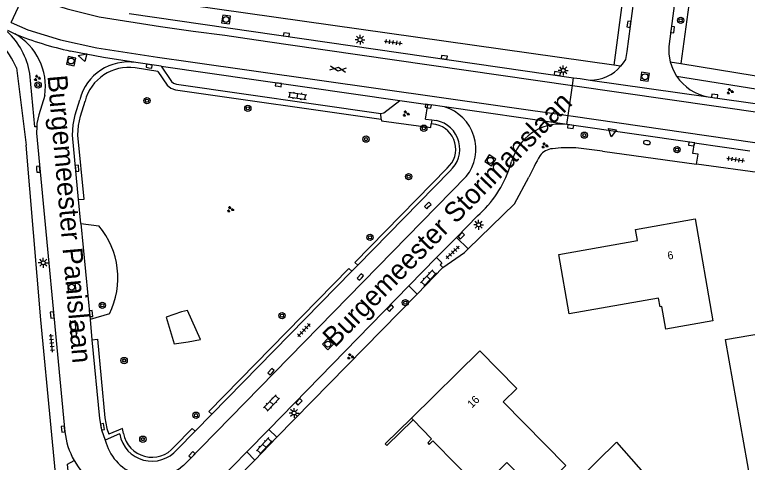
# Model space of a CAD drawing. Extents: x 136000 to 138005, y 398500 to 400500.
# Drawn here: x 137759.2 to 137852, y 398873.8 to 398930.5 of the extents above; entities that cross this region are included whole.
import ezdxf

# ---------------------------------------------------------------- set-up
doc = ezdxf.new("R2010")
doc.units = 0
for name, color, linetype in [('gg-afsc-erfafscheiding', 7, 'Continuous'), ('gg-afsc-muur', 7, 'Continuous'), ('gg-anno-huisnummerreeks BGT', 7, 'Continuous'), ('gg-anno-openbare ruimte label', 7, 'Continuous'), ('gg-bbg-gedigitaliseerde bebouwing', 7, 'Continuous'), ('gg-bbg-gedigitaliseerde bijgebouw', 7, 'Continuous'), ('gg-bbg-hoofdgebouw', 7, 'Continuous'), ('gg-knt-verharding', 7, 'Continuous'), ('gg-knt-verharding nz', 7, 'Continuous'), ('gt-grn-groengrens', 7, 'Continuous'), ('gt-grn-vlakafsluiter', 7, 'Continuous'), ('gt-grn-weggrens', 7, 'Continuous'), ('gt-symb-boom', 7, 'Continuous'), ('gt-symb-brandkraan', 7, 'Continuous'), ('gt-symb-gesloten verharding', 7, 'Continuous'), ('gt-symb-groenvak', 7, 'Continuous'), ('gt-symb-klinker verharding', 7, 'Continuous'), ('gt-symb-kolk', 7, 'Continuous'), ('gt-symb-lichtmast', 7, 'Continuous'), ('gt-symb-rioolschacht', 7, 'Continuous'), ('gt-symb-tegel verharding', 7, 'Continuous'), ('gt-symb-waterafsluiter', 7, 'Continuous')]:
    doc.layers.add(name, color=color, linetype=linetype)

# ---------------------------------------------------------------- blocks, each defined once
blk = doc.blocks.new('gt0-BOOM')
at = {"layer": 'gt-symb-boom'}
for radius in [0.4, 0.2]:
    blk.add_circle((0, 0), radius, dxfattribs=at)
blk = doc.blocks.new('gt0-KOLK')
at = {"layer": 'gt-symb-kolk'}
blk.add_lwpolyline([(0, 0), (0.375, 0), (0.375, 0.4), (-0.375, 0.4), (-0.375, 0), (0, 0)], dxfattribs=at)
blk = doc.blocks.new('gt0-LMAST')
at = {"layer": 'gt-symb-lichtmast'}
for p, q in [((-0.182, 0.173), (-0.447, 0.438)), ((-0.005, 0.246), (-0.005, 0.621)), ((0.172, 0.173), (0.437, 0.438)), ((-0.255, -0.004), (-0.63, -0.004)), ((-0.182, -0.181), (-0.447, -0.446)), ((-0.005, -0.254), (-0.005, -0.629)), ((0.437, -0.446), (0.172, -0.181)), ((0.245, -0.004), (0.62, -0.004))]:
    blk.add_line(p, q, dxfattribs=at)
blk.add_circle((-0.005, -0.004), 0.25, dxfattribs=at)
blk = doc.blocks.new('gt0-RS')
at = {"layer": 'gt-symb-rioolschacht'}
blk.add_lwpolyline([(-0.5, -0.5), (0.5, -0.5), (0.5, 0.5), (-0.5, 0.5)], close=True, dxfattribs=at)
blk.add_circle((0, 0), 0.375, dxfattribs=at)
blk = doc.blocks.new('gt0-WAFSL')
at = {"layer": 'gt-symb-waterafsluiter'}
for p, q in [((-0.5, -0.333), (0, 0.667)), ((0, 0.667), (0.5, -0.333)), ((0.5, -0.333), (-0.5, -0.333))]:
    blk.add_line(p, q, dxfattribs=at)
blk = doc.blocks.new('gt0-GRVAK')
at = {"layer": 'gt-symb-groenvak'}
for p, q in [((-0.11, 0.189), (-0.228, 0.24)), ((-0.182, 0.153), (0.088, 0.153)), ((-0.091, 0.211), (-0.156, 0.322)), ((-0.047, 0.214), (-0.047, 0.393)), ((-0.004, 0.211), (0.061, 0.322)), ((0.015, 0.189), (0.133, 0.24)), ((0.262, -0.052), (0.197, 0.059)), ((0.305, -0.049), (0.305, 0.13)), ((0.349, -0.052), (0.414, 0.059)), ((-0.245, -0.228), (-0.363, -0.177)), ((-0.318, -0.264), (-0.047, -0.264)), ((-0.226, -0.206), (-0.291, -0.095)), ((-0.183, -0.203), (-0.183, -0.024)), ((-0.139, -0.206), (-0.074, -0.095)), ((-0.12, -0.228), (-0.002, -0.177)), ((0.243, -0.074), (0.125, -0.023)), ((0.17, -0.11), (0.441, -0.11)), ((0.368, -0.074), (0.486, -0.023))]:
    blk.add_line(p, q, dxfattribs=at)
blk = doc.blocks.new('gt0-BR')
at = {"layer": 'gt-symb-brandkraan'}
for centre, radius, start, end in [((-0.244, 0), 0.206, 107.56694, 252.43307), ((0.599, -2.664), 3, 106.89205, 107.56694), ((0, -0.691), 0.938, 73.10799, 106.89205), ((-0.599, -2.664), 3, 72.43309, 73.10799), ((0.244, 0), 0.206, 287.56695, 72.43309), ((0.599, 2.664), 3, 252.43307, 253.10797), ((0, 0.691), 0.938, 253.10797, 286.89206), ((-0.599, 2.664), 3, 286.89206, 287.56695)]:
    blk.add_arc(centre, radius, start, end, dxfattribs=at)
blk = doc.blocks.new('gt0-KL1')
at = {"layer": 'gt-symb-klinker verharding'}
for p, q in [((-1.15, 0.3), (1.15, 0.3)), ((-1, -0.3), (-1, 0.3)), ((-0.5, 0.3), (-0.5, 0.45)), ((0, -0.3), (0, 0.3)), ((0.5, 0.3), (0.5, 0.45)), ((1, -0.3), (1, 0.3)), ((-1.15, -0.3), (1.15, -0.3)), ((-0.5, -0.45), (-0.5, -0.3)), ((0.5, -0.45), (0.5, -0.3))]:
    blk.add_line(p, q, dxfattribs=at)
blk = doc.blocks.new('gt0-GESVH1')
at = {"layer": 'gt-symb-gesloten verharding'}
for p, q in [((-0.992, -0.261), (0.008, 0.239)), ((0.008, -0.261), (-0.992, 0.239)), ((0.008, 0.239), (1.008, -0.261)), ((1.008, 0.239), (0.008, -0.261))]:
    blk.add_line(p, q, dxfattribs=at)
blk = doc.blocks.new('gt0-TEG1')
at = {"layer": 'gt-symb-tegel verharding'}
for p, q in [((-1.125, 0), (1.125, 0)), ((-0.9, -0.25), (-0.9, 0.25)), ((-0.45, -0.25), (-0.45, 0.25)), ((0, -0.25), (0, 0.25)), ((0.45, -0.25), (0.45, 0.25)), ((0.9, -0.25), (0.9, 0.25))]:
    blk.add_line(p, q, dxfattribs=at)

msp = doc.modelspace()

# ---------------------------------------------------------------- linework, layer by layer
at = {"layer": 'gg-afsc-erfafscheiding'}
msp.add_line((137849.172, 398966.355), (137843.585, 398924.323), dxfattribs=at)
at = {"layer": 'gg-afsc-muur'}
msp.add_lwpolyline([(137809.669, 398879.17), (137806.335, 398875.945), (137806.14, 398876.145), (137809.445, 398879.401)], dxfattribs=at)
at = {"layer": 'gg-bbg-gedigitaliseerde bebouwing'}
msp.add_lwpolyline([(137812.16, 398876.54), (137818.147, 398870.434), (137821.554, 398873.772), (137825.397, 398869.848), (137829.008, 398873.386), (137821.075, 398881.484), (137822.794, 398883.168)], dxfattribs=at)
at = {"layer": 'gg-bbg-gedigitaliseerde bijgebouw'}
for points in [[(137849.241, 398889.354), (137853.928, 398890.181), (137857.16, 398871.867), (137852.473, 398871.04), (137849.241, 398889.354)], [(137830.527, 398871.557), (137835.417, 398876.348), (137843.761, 398866.846), (137835.533, 398859.624), (137832.545, 398862.673), (137835.956, 398866.016), (137830.527, 398871.557)]]:
    msp.add_lwpolyline(points, dxfattribs=at)
at = {"layer": 'gg-bbg-hoofdgebouw'}
for p, q in [((137809.445, 398879.401), (137818.136, 398887.922)), ((137818.136, 398887.922), (137822.794, 398883.168)), ((137809.445, 398879.401), (137809.669, 398879.17)), ((137809.669, 398879.17), (137812.012, 398876.76))]:
    msp.add_line(p, q, dxfattribs=at)
for points in [[(137847.63, 398891.74), (137841.68, 398890.69), (137841.18, 398893.52), (137840.95, 398893.48), (137840.76, 398894.59), (137829.43, 398892.6), (137828.1, 398900.12), (137838.07, 398901.88), (137837.81, 398903.31), (137845.37, 398904.64), (137847.63, 398891.74)], [(137812.012, 398876.76), (137811.51, 398876.27), (137811.69, 398876.08), (137812.16, 398876.54)]]:
    msp.add_lwpolyline(points, dxfattribs=at)
at = {"layer": 'gg-knt-verharding'}
for p, q in [((137841.7, 398974.74), (137835.09, 398924.09)), ((137773.71, 398930.63), (137829.994, 398922.515)), ((137758.305, 398928.523), (137759.232, 398928.073)), ((137777.756, 398923.963), (137774.576, 398924.44)), ((137777.756, 398923.963), (137807.979, 398919.631)), ((137842.224, 398924.546), (137843.585, 398924.323)), ((137759.438, 398923.775), (137760.686, 398913.953)), ((137829.994, 398922.515), (137830.813, 398922.397)), ((137830.813, 398922.397), (137832.087, 398922.216)), ((137832.087, 398922.216), (137847.038, 398920.096)), ((137843.035, 398922.72), (137854.113, 398920.924)), ((137807.979, 398919.631), (137811.531, 398919.121)), ((137847.038, 398920.096), (137853.852, 398919.114)), ((137811.217, 398917.275), (137811.531, 398919.121)), ((137811.531, 398919.121), (137811.912, 398919.065)), ((137813.652, 398918.816), (137811.912, 398919.065)), ((137828.872, 398916.635), (137813.652, 398918.816)), ((137811.217, 398917.275), (137812.019, 398917.169)), ((137812.019, 398917.169), (137812.622, 398917.09)), ((137829.138, 398916.599), (137828.872, 398916.635)), ((137829.44, 398916.559), (137829.138, 398916.599)), ((137845.316, 398914.26), (137829.44, 398916.559)), ((137845.316, 398914.26), (137852.313, 398913.247)), ((137821.9, 398911.177), (137822.139, 398911.907)), ((137854.254, 398910.379), (137845.561, 398911.588)), ((137814.306, 398910.693), (137802.649, 398898.784)), ((137767.593, 398904.052), (137767.303, 398907.088)), ((137815.147, 398902.281), (137817.824, 398905.018)), ((137767.593, 398904.052), (137768.756, 398891.889)), ((137812.647, 398899.725), (137815.147, 398902.281)), ((137815.147, 398902.281), (137816.63, 398900.833)), ((137812.647, 398899.725), (137809.139, 398896.138)), ((137801.893, 398898.012), (137784.16, 398879.896)), ((137802.649, 398898.784), (137801.893, 398898.012)), ((137809.139, 398896.138), (137791.382, 398877.982)), ((137810.199, 398895.121), (137809.139, 398896.138)), ((137768.756, 398891.889), (137769.002, 398889.316)), ((137784.16, 398879.896), (137782.06, 398877.751)), ((137782.06, 398877.751), (137779.791, 398875.433)), ((137791.382, 398877.982), (137788.615, 398875.153)), ((137791.382, 398877.982), (137792.416, 398876.982)), ((137792.416, 398876.982), (137789.624, 398874.098)), ((137784.811, 398871.263), (137788.615, 398875.153)), ((137789.624, 398874.098), (137788.615, 398875.153))]:
    msp.add_line(p, q, dxfattribs=at)
for points in [[(137843.06, 398973.991), (137836.74, 398925.85), (137836.54, 398924.83), (137836.267, 398924.384), (137835.948, 398923.968)], [(137847.287, 398966.575), (137842.05, 398926.49), (137842.058, 398925.511), (137842.224, 398924.546)], [(137835.09, 398924.09), (137770.818, 398933.23), (137768.26, 398933.809), (137765.748, 398934.561)], [(137774.576, 398924.44), (137770.481, 398925.08), (137766.263, 398925.895)], [(137777.756, 398923.963), (137779.07, 398922.04), (137779.33, 398921.81), (137779.72, 398921.68), (137805.57, 398917.97)], [(137842.224, 398924.546), (137842.545, 398923.619), (137843.035, 398922.72)], [(137843.585, 398924.323), (137896.72, 398915.63), (137905.34, 398913.48), (137916.2, 398909.94), (137941.68, 398896.23), (137941.953, 398896.066)], [(137762.006, 398916.287), (137761.782, 398916.293), (137761.135, 398923.048)], [(137763.028, 398920.283), (137762.273, 398917.81), (137762.03, 398916.723), (137762.006, 398916.287)], [(137767.303, 398907.088), (137766.523, 398915.244), (137766.607, 398916.546), (137766.873, 398917.811), (137767.455, 398919.733)], [(137805.57, 398917.97), (137805.97, 398918.05), (137807.979, 398919.631)], [(137762.006, 398916.287), (137761.961, 398915.488), (137765.576, 398877.677)], [(137764.04, 398861.22), (137765.126, 398864.476), (137762.521, 398891.862), (137760.686, 398913.953)], [(137845.561, 398911.588), (137845.775, 398912.819), (137845.077, 398912.908), (137845.316, 398914.26)], [(137816.396, 398909.991), (137780.932, 398873.722), (137780.577, 398873.393), (137780.195, 398873.092)], [(137812.647, 398899.725), (137813.286, 398899.061), (137813.087, 398898.811), (137813.449, 398898.474)], [(137769.002, 398889.316), (137769.955, 398879.361), (137770.203, 398877.908), (137770.688, 398876.609)], [(137772.514, 398877.35), (137772.506, 398877.392), (137770.688, 398876.609)], [(137766.172, 398862.515), (137766.804, 398864.317), (137765.913, 398873.55), (137766.744, 398874.046)], [(137766.744, 398874.046), (137767.262, 398873.24), (137769.134, 398870.678)]]:
    msp.add_lwpolyline(points, dxfattribs=at)
for centre, radius, start, end in [((137751.818, 398921.458), 9.452, 9.68569, 47.06572), ((137775.062, 398966.738), 41.78, 247.73495, 257.84212), ((137755.426, 398921.398), 7.684, 351.65442, 60.30473), ((137749.151, 398919.363), 11.193, 23.21213, 42.06111), ((137773.618, 398918.149), 6.364, 81.3453, 165.58432), ((137832.148, 398927.212), 4.997, 269.3017, 319.5124), ((137848.081, 398926.053), 6.047, 213.44234, 260.06731), ((137812.011, 398913.467), 5.595, 321.59999, 72.94458), ((137811.88, 398913.474), 3.691, 311.10096, 78.39586), ((137828.397, 398910.154), 6.499, 85.80726, 164.3468), ((137808.557, 398915.579), 14.05, 311.2658, 341.74136), ((137774.517, 398878.55), 8.983, 185.57468, 210.08863), ((137776.605, 398878.108), 4.16, 190.49985, 319.98357), ((137776.615, 398878.023), 6.093, 193.41717, 305.98014)]:
    msp.add_arc(centre, radius, start, end, dxfattribs=at)
at = {"layer": 'gg-knt-verharding nz'}
msp.add_line((137829.855, 398921.55), (137885.395, 398913.552), dxfattribs=at)
for points in [[(137760.437, 398933.154), (137762.029, 398932.497), (137765.853, 398931.234), (137769.893, 398930.246), (137777.66, 398929.005), (137781.797, 398928.432), (137785.807, 398927.897), (137789.779, 398927.311), (137793.827, 398926.739), (137829.855, 398921.55)], [(137758.768, 398929.528), (137760.864, 398928.563), (137765.031, 398927.313), (137769.634, 398926.299), (137777.286, 398925.115), (137781.472, 398924.542), (137829.3, 398917.716)], [(137829.3, 398917.716), (137829.929, 398917.626), (137883.781, 398909.832)]]:
    msp.add_lwpolyline(points, dxfattribs=at)
at = {"layer": 'gt-grn-groengrens'}
for p, q in [((137777.35, 398923.316), (137774.471, 398923.748)), ((137805.634, 398917.254), (137805.57, 398917.97)), ((137812.019, 398917.169), (137811.954, 398916.673)), ((137812.538, 398916.597), (137811.954, 398916.673)), ((137833.646, 398913.207), (137830.272, 398913.638)), ((137833.646, 398913.207), (137845.561, 398911.588)), ((137822.498, 398906.548), (137824.304, 398909.904)), ((137816.63, 398900.833), (137822.498, 398906.548)), ((137767.593, 398904.052), (137769.875, 398903.748)), ((137810.199, 398895.121), (137792.416, 398876.982)), ((137771.214, 398892.616), (137768.756, 398891.889)), ((137786.113, 398870.525), (137789.624, 398874.098))]:
    msp.add_line(p, q, dxfattribs=at)
for points in [[(137777.35, 398923.316), (137778.541, 398921.573), (137778.973, 398921.191), (137779.558, 398920.996), (137805.634, 398917.254)], [(137767.303, 398907.088), (137768, 398907.155), (137767.225, 398915.255), (137767.302, 398916.451), (137767.552, 398917.637), (137768.125, 398919.53)], [(137805.634, 398917.254), (137805.65, 398917.073), (137811.895, 398916.225), (137811.954, 398916.673)], [(137813.977, 398911.07), (137802.292, 398899.133), (137802.649, 398898.784)], [(137801.893, 398898.012), (137801.536, 398898.361), (137783.803, 398880.246), (137784.16, 398879.896)], [(137779.423, 398888.803), (137781.169, 398889.078), (137782.731, 398889.354), (137781.077, 398893.03), (137780.342, 398892.846), (137778.412, 398892.203), (137779.423, 398888.803)], [(137769.002, 398889.316), (137769.699, 398889.382), (137770.649, 398879.453), (137770.882, 398878.091), (137771.157, 398877.355)], [(137773.006, 398877.441), (137772.881, 398878.098), (137771.157, 398877.355)], [(137782.06, 398877.751), (137781.703, 398878.101), (137779.408, 398875.755)]]:
    msp.add_lwpolyline(points, dxfattribs=at)
for centre, radius, start, end in [((137773.63, 398918.13), 5.68, 81.48839, 165.73325), ((137811.88, 398913.475), 3.191, 311.09508, 78.09181), ((137827.498, 398911.358), 2.179, 94.91638, 143.60799), ((137829.588, 398891.933), 21.716, 88.19633, 96.0201), ((137865.701, 398889.954), 45.953, 150.40218, 154.27002), ((137762.034, 398897.158), 10.243, 333.67497, 40.04264), ((137776.605, 398878.107), 3.66, 190.49214, 319.99959)]:
    msp.add_arc(centre, radius, start, end, dxfattribs=at)
at = {"layer": 'gt-grn-vlakafsluiter'}
msp.add_line((137813.449, 398898.474), (137810.199, 398895.121), dxfattribs=at)
msp.add_lwpolyline([(137813.449, 398898.474), (137816.183, 398900.379), (137816.63, 398900.833)], dxfattribs=at)
at = {"layer": 'gt-grn-weggrens'}
for p, q in [((137758.768, 398929.528), (137760.437, 398933.154)), ((137835.948, 398923.968), (137835.09, 398924.09)), ((137829.855, 398921.55), (137829.994, 398922.515)), ((137829.3, 398917.716), (137829.855, 398921.55)), ((137829.138, 398916.599), (137829.3, 398917.716))]:
    msp.add_line(p, q, dxfattribs=at)

# ---------------------------------------------------------------- block references
at = {"layer": 'gt-symb-boom'}
for p in [(137843.549, 398929.785), (137762.18, 398921.587), (137775.968, 398919.616), (137788.737, 398918.647), (137811.023, 398916.117), (137831.345, 398915.239), (137803.71, 398914.735), (137843.09, 398913.393), (137809.1, 398909.987), (137804.218, 398902.305), (137808.688, 398894.035), (137770.31, 398893.689), (137793.067, 398892.369), (137773.077, 398886.699), (137782.183, 398879.77), (137775.448, 398876.731)]:
    msp.add_blockref('gt0-BOOM', p, dxfattribs=at)
at = {"layer": 'gt-symb-brandkraan', "rotation": 171.7807907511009}
msp.add_blockref('gt0-BR', (137839.267, 398914.297), dxfattribs=at)
at = {"layer": 'gt-symb-gesloten verharding', "rotation": -8.16250946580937}
msp.add_blockref('gt0-GESVH1', (137800.161, 398923.613), dxfattribs=at)
at = {"layer": 'gt-symb-groenvak'}
for p in [(137762.058, 398922.485), (137849.78, 398920.791), (137808.751, 398917.957), (137826.311, 398913.921), (137786.51, 398905.835), (137801.701, 398887.203)]:
    msp.add_blockref('gt0-GRVAK', p, dxfattribs=at)
at = {"layer": 'gt-symb-klinker verharding'}
for p, rotation in [((137795.029, 398920.226), -8.162509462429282), ((137811.614, 398897.161), 46.662043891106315), ((137766.686, 398890.633), 95.45391889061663), ((137791.745, 398881.318), 46.662043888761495), ((137790.83, 398875.885), 46.662043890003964)]:
    msp.add_blockref('gt0-KL1', p, dxfattribs=dict(at, rotation=rotation))
at = {"layer": 'gt-symb-kolk'}
for p, rotation in [((137837.187, 398929.26), 82.53402593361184), ((137842.724, 398928.577), 82.53402593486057), ((137793.596, 398927.771), -8.16250946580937), ((137813.577, 398924.9), -8.162509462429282), ((137776.215, 398923.78), -8.162509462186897), ((137827.905, 398922.837), -8.16250946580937), ((137792.581, 398921.433), -8.16250946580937), ((137847.82, 398919.987), -8.162509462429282), ((137811.553, 398918.714), -8.16250946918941), ((137829.577, 398916.135), -8.16250946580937), ((137844.895, 398913.923), -8.16250946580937), ((137761.997, 398910.907), -84.54608111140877), ((137766.923, 398911.021), -84.54608111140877), ((137811.676, 398906.2), 46.62038199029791), ((137815.903, 398902.355), 45.405196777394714), ((137803.124, 398897.135), 46.53940290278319), ((137806.937, 398893.184), 45.648297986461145), ((137763.761, 398892.44), -84.54608111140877), ((137768.671, 398892.628), -84.54608111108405), ((137791.811, 398885.15), 46.743070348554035), ((137795.35, 398881.324), 45.405196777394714), ((137770.141, 398878.274), -80.33049474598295), ((137765.145, 398877.984), -84.54608111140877), ((137781.809, 398874.627), 45.405196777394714)]:
    msp.add_blockref('gt0-KOLK', p, dxfattribs=dict(at, rotation=rotation))
at = {"layer": 'gt-symb-lichtmast'}
for p in [(137802.95, 398927.332), (137828.681, 398923.443), (137817.965, 398903.89), (137762.832, 398899.076), (137794.599, 398880.052)]:
    msp.add_blockref('gt0-LMAST', p, dxfattribs=at)
at = {"layer": 'gt-symb-rioolschacht'}
for p, rotation in [((137785.976, 398929.891), -8.16250946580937), ((137766.351, 398924.629), -12.242859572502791), ((137839.025, 398922.639), -8.105793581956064), ((137819.452, 398912.047), -32.83164893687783), ((137766.435, 398895.988), 5.453918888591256), ((137798.88, 398888.775), 45.405196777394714)]:
    msp.add_blockref('gt0-RS', p, dxfattribs=dict(at, rotation=rotation))
at = {"layer": 'gt-symb-tegel verharding'}
for p, rotation in [((137807.149, 398927), -8.16250946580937), ((137850.518, 398912.152), -8.16250946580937), ((137814.686, 398900.389), 43.41898922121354), ((137795.847, 398890.543), 46.662043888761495), ((137763.915, 398888.897), 95.45391888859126)]:
    msp.add_blockref('gt0-TEG1', p, dxfattribs=dict(at, rotation=rotation))
at = {"layer": 'gt-symb-waterafsluiter'}
for p, rotation in [((137767.891, 398925.143), 74.81021283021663), ((137834.859, 398915.673), 171.7807907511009)]:
    msp.add_blockref('gt0-WAFSL', p, dxfattribs=dict(at, rotation=rotation))

# ---------------------------------------------------------------- texts
at = {"layer": 'gg-anno-huisnummerreeks BGT'}
for s, rotation, p in [('6', 9.9, (137841.964, 398899.473)), ('16', 44.4, (137817.108, 398880.612))]:
    msp.add_text(s, height=1, rotation=rotation, dxfattribs=at).set_placement(p)
at = {"layer": 'gg-anno-openbare ruimte label'}
for s, rotation, p in [('Burgemeester Panislaan', 275, (137763.365, 398922.753)), ('Burgemeester Storimanslaan', 45.7, (137799.751, 398888.223))]:
    msp.add_text(s, height=2.5, rotation=rotation, dxfattribs=at).set_placement(p)

doc.saveas('drawing.dxf')
